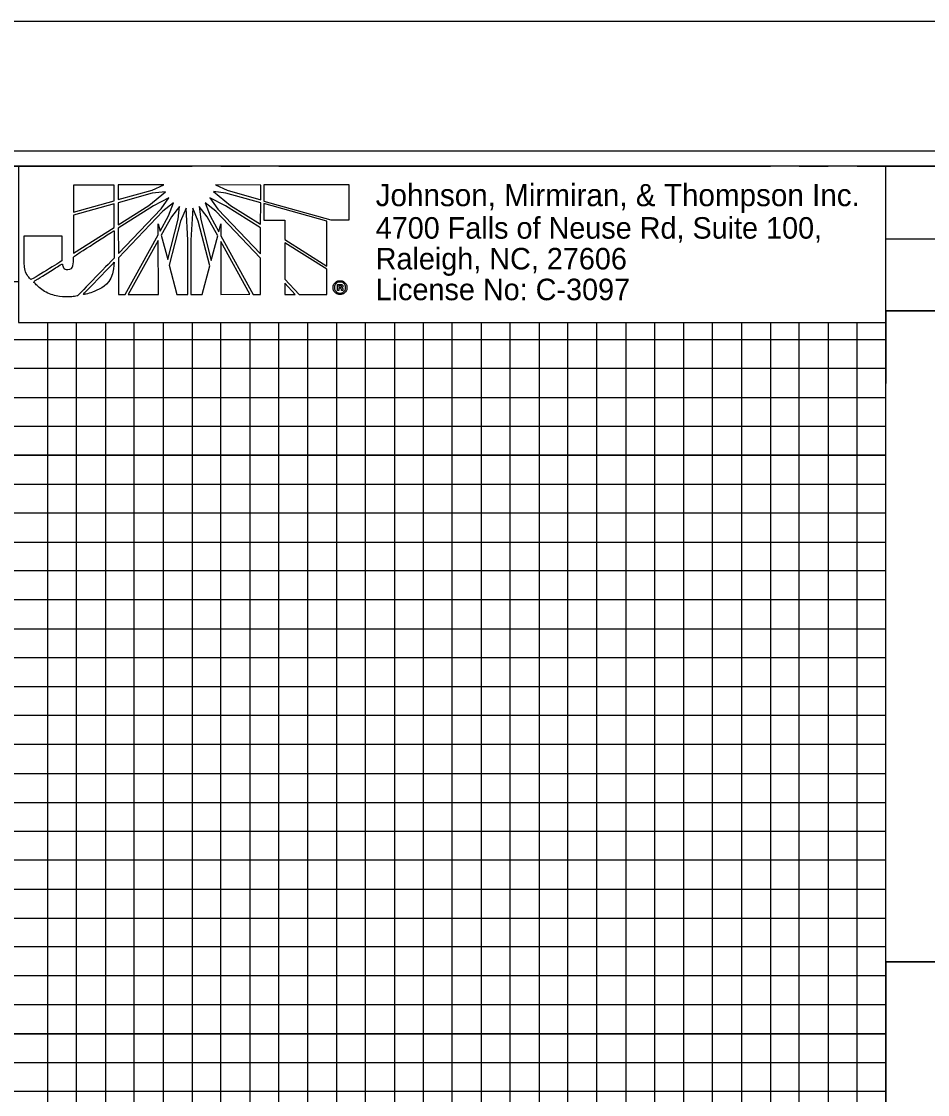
# Model space of a CAD drawing. Extents: x 1648862 to 1650855, y 808691 to 809791.
# Drawn here: x 1650179.8 to 1650336.5, y 809605.5 to 809791 of the extents above; entities that cross this region are included whole.
import ezdxf

# ---------------------------------------------------------------- set-up
doc = ezdxf.new("R2010")
doc.units = 0
for name, color, linetype in [('Prop Dimension Text', 7, 'Continuous'), ('Sheet Cutting Line CELL', 7, 'Continuous'), ('Sheet DOT Grid CELL', 7, 'Continuous'), ('Sheet Plan CELL', 7, 'Continuous'), ('Sheet Plot Border Inside CELL', 7, 'Continuous'), ('Sheet Plot Border Outside CELL', 7, 'Continuous'), ('Sheet Profile CELL', 7, 'Continuous'), ('Sheet Profile Grid Major CELL', 7, 'Continuous'), ('Sheet Profile Grid Middle CELL', 7, 'Continuous'), ('Sheet Profile Grid Minor CELL', 7, 'Continuous'), ('Sheet Sticker Exception Certification CELL', 7, 'Continuous')]:
    doc.layers.add(name, color=color, linetype=linetype)

msp = doc.modelspace()

# ---------------------------------------------------------------- linework, layer by layer
at = {"layer": 'Prop Dimension Text'}
for p, q in [((1650195.79, 809762.71), (1650188.77, 809762.7)), ((1650188.77, 809762.7), (1650188.77, 809758.05)), ((1650195.79, 809760), (1650195.79, 809762.71)), ((1650204.41, 809762.75), (1650196.52, 809762.75)), ((1650196.52, 809762.75), (1650196.52, 809760.23)), ((1650196.52, 809760.23), (1650202.4, 809761.86)), ((1650202.4, 809761.31), (1650196.52, 809759.69)), ((1650201.79, 809759.23), (1650204.69, 809761.59)), ((1650202.4, 809761.86), (1650204.41, 809762.75)), ((1650204.69, 809761.59), (1650202.4, 809761.31)), ((1650212.96, 809761.6), (1650215.9, 809759.2)), ((1650215.13, 809761.33), (1650212.96, 809761.6)), ((1650221.14, 809762.73), (1650213.35, 809762.76)), ((1650213.35, 809762.76), (1650215.32, 809761.84)), ((1650221.14, 809759.68), (1650215.13, 809761.33)), ((1650215.32, 809761.84), (1650221.14, 809760.21)), ((1650221.14, 809760.21), (1650221.14, 809762.73)), ((1650236.43, 809762.78), (1650221.68, 809762.77)), ((1650221.68, 809762.77), (1650221.68, 809760.06)), ((1650236.44, 809756.74), (1650236.43, 809762.78)), ((1650188.77, 809758.05), (1650195.79, 809760)), ((1650195.79, 809759.49), (1650188.77, 809757.52)), ((1650195.79, 809755.43), (1650195.79, 809759.49)), ((1650196.52, 809759.69), (1650196.52, 809755.89)), ((1650196.52, 809755.89), (1650201.79, 809759.23)), ((1650202.6, 809759.15), (1650196.52, 809755.28)), ((1650205.27, 809760.51), (1650202.6, 809759.15)), ((1650203.92, 809758.61), (1650205.27, 809760.51)), ((1650206.08, 809759.66), (1650204.22, 809758.22)), ((1650205.23, 809757.42), (1650206.08, 809759.66)), ((1650211.53, 809759.67), (1650212.39, 809757.42)), ((1650213.39, 809758.23), (1650211.53, 809759.67)), ((1650212.35, 809760.51), (1650213.71, 809758.58)), ((1650215.06, 809759.16), (1650212.35, 809760.51)), ((1650221.1, 809755.33), (1650215.06, 809759.16)), ((1650215.9, 809759.2), (1650221.1, 809755.96)), ((1650221.1, 809755.96), (1650221.14, 809759.68)), ((1650221.68, 809760.06), (1650221.68, 809759.98)), ((1650221.68, 809759.98), (1650233.3, 809756.74)), ((1650221.68, 809759.56), (1650221.68, 809759.52)), ((1650232.56, 809756.47), (1650221.68, 809759.56)), ((1650221.68, 809759.52), (1650221.69, 809756.69)), ((1650188.77, 809757.52), (1650188.78, 809750.97)), ((1650196.53, 809750.9), (1650203.92, 809758.61)), ((1650204.22, 809758.22), (1650196.53, 809750.16)), ((1650203.76, 809754.74), (1650205.23, 809757.42)), ((1650207.09, 809759.04), (1650205.7, 809757.25)), ((1650206.9, 809756.87), (1650207.09, 809759.04)), ((1650208.25, 809758.73), (1650207.29, 809756.48)), ((1650208.56, 809753.19), (1650208.25, 809758.73)), ((1650209.41, 809758.73), (1650209.05, 809753.19)), ((1650210.34, 809756.48), (1650209.41, 809758.73)), ((1650210.53, 809759.04), (1650210.77, 809756.8)), ((1650211.89, 809757.26), (1650210.53, 809759.04)), ((1650213.71, 809753.97), (1650211.89, 809757.26)), ((1650212.39, 809757.42), (1650213.89, 809754.63)), ((1650221.1, 809750.11), (1650213.39, 809758.23)), ((1650213.71, 809758.58), (1650221.1, 809750.84)), ((1650188.78, 809750.97), (1650195.79, 809755.43)), ((1650203.41, 809754.16), (1650203.41, 809756.01)), ((1650203.41, 809756.01), (1650203.76, 809754.74)), ((1650205.7, 809757.25), (1650203.96, 809754.08)), ((1650205.09, 809749.87), (1650206.9, 809756.87)), ((1650207.29, 809756.48), (1650205.32, 809748.89)), ((1650212.36, 809748.78), (1650210.34, 809756.48)), ((1650210.77, 809756.8), (1650212.59, 809749.71)), ((1650213.89, 809754.63), (1650214.25, 809756.02)), ((1650214.25, 809756.02), (1650214.25, 809753.97)), ((1650221.69, 809756.69), (1650225.29, 809756.69)), ((1650225.29, 809756.69), (1650225.29, 809753.32)), ((1650232.57, 809748.72), (1650232.56, 809756.47)), ((1650233.3, 809756.74), (1650236.44, 809756.74)), ((1650196.52, 809755.28), (1650196.53, 809750.9)), ((1650197.69, 809743.79), (1650203.41, 809754.16)), ((1650203.96, 809754.08), (1650205.09, 809749.87)), ((1650212.59, 809749.71), (1650213.71, 809753.97)), ((1650214.25, 809753.97), (1650219.87, 809743.81)), ((1650221.1, 809750.84), (1650221.1, 809755.33)), ((1650203.42, 809753.15), (1650198.24, 809743.79)), ((1650203.47, 809743.8), (1650203.42, 809753.15)), ((1650208.57, 809743.84), (1650208.56, 809753.19)), ((1650209.05, 809753.19), (1650209.06, 809743.84)), ((1650219.29, 809743.85), (1650214.25, 809752.97)), ((1650214.25, 809752.97), (1650214.26, 809743.84)), ((1650225.29, 809753.32), (1650232.57, 809748.72)), ((1650225.29, 809752.74), (1650225.3, 809746.47)), ((1650232.57, 809748.18), (1650225.29, 809752.74)), ((1650196.53, 809750.16), (1650196.53, 809743.79)), ((1650221.11, 809743.81), (1650221.1, 809750.11)), ((1650205.32, 809748.89), (1650206.64, 809743.83)), ((1650211.01, 809743.84), (1650212.36, 809748.78)), ((1650232.57, 809743.82), (1650232.57, 809748.18)), ((1650225.3, 809746.47), (1650227.81, 809743.82)), ((1650234.86, 809746.19), (1650234.86, 809745.97)), ((1650234.86, 809745.97), (1650234.86, 809746.19)), ((1650227.12, 809743.82), (1650225.3, 809745.78)), ((1650225.3, 809745.78), (1650225.3, 809743.82)), ((1650234.42, 809744.49), (1650234.42, 809745.56)), ((1650234.42, 809745.56), (1650234.86, 809745.56)), ((1650234.66, 809744.49), (1650234.42, 809744.49)), ((1650234.86, 809745.36), (1650234.66, 809745.36)), ((1650234.66, 809745.36), (1650234.66, 809745.1)), ((1650234.66, 809745.1), (1650234.86, 809745.1)), ((1650234.86, 809744.91), (1650234.66, 809744.91)), ((1650234.66, 809744.91), (1650234.66, 809744.49)), ((1650234.86, 809745.56), (1650234.86, 809745.36)), ((1650234.86, 809745.36), (1650234.86, 809745.56)), ((1650234.86, 809745.56), (1650234.92, 809745.56)), ((1650234.89, 809745.36), (1650234.86, 809745.36)), ((1650234.86, 809745.1), (1650234.86, 809744.91)), ((1650234.86, 809744.91), (1650234.86, 809745.1)), ((1650234.86, 809745.1), (1650234.87, 809745.1)), ((1650234.87, 809744.91), (1650234.86, 809744.91)), ((1650196.53, 809743.79), (1650197.69, 809743.79)), ((1650198.24, 809743.79), (1650203.47, 809743.8)), ((1650206.64, 809743.83), (1650208.57, 809743.84)), ((1650209.06, 809743.84), (1650211.01, 809743.84)), ((1650214.26, 809743.84), (1650219.29, 809743.85)), ((1650219.87, 809743.81), (1650221.11, 809743.81)), ((1650225.3, 809743.82), (1650227.12, 809743.82)), ((1650227.81, 809743.82), (1650232.57, 809743.82)), ((1650234.86, 809744.07), (1650234.86, 809743.83)), ((1650234.86, 809743.83), (1650234.86, 809744.07)), ((1650234.86, 809744.07), (1650234.87, 809744.07)), ((1650234.87, 809743.83), (1650234.86, 809743.83))]:
    msp.add_line(p, q, dxfattribs=at)
msp.add_lwpolyline([(1650179.28, 809738.96), (1650329.23, 809738.96), (1650329.23, 809766.02), (1650179.28, 809766.02)], close=True, dxfattribs=at)
for points in [[(1650188.77, 809758.05), (1650195.79, 809760), (1650195.79, 809762.71), (1650188.77, 809762.7), (1650188.77, 809758.05)], [(1650202.4, 809761.86), (1650204.41, 809762.75), (1650196.52, 809762.75), (1650196.52, 809760.23), (1650202.4, 809761.86)], [(1650196.52, 809759.69), (1650196.52, 809755.89), (1650201.79, 809759.23), (1650204.69, 809761.59), (1650202.4, 809761.31), (1650196.52, 809759.69)], [(1650212.96, 809761.6), (1650215.9, 809759.2), (1650221.1, 809755.96), (1650221.14, 809759.68), (1650215.13, 809761.33), (1650212.96, 809761.6)], [(1650215.32, 809761.84), (1650221.14, 809760.21), (1650221.14, 809762.73), (1650213.35, 809762.76), (1650215.32, 809761.84)], [(1650236.43, 809762.78), (1650221.68, 809762.77), (1650221.68, 809760.06), (1650221.68, 809759.98), (1650233.3, 809756.74), (1650236.44, 809756.74), (1650236.43, 809762.78)], [(1650188.78, 809750.97), (1650195.79, 809755.43), (1650195.79, 809759.49), (1650188.77, 809757.52), (1650188.78, 809750.97)], [(1650196.52, 809755.28), (1650196.53, 809750.9), (1650203.92, 809758.61), (1650205.27, 809760.51), (1650202.6, 809759.15), (1650196.52, 809755.28)], [(1650206.08, 809759.66), (1650204.22, 809758.22), (1650196.53, 809750.16), (1650196.53, 809743.79), (1650197.69, 809743.79), (1650203.41, 809754.16), (1650203.41, 809756.01), (1650203.76, 809754.74), (1650205.23, 809757.42), (1650206.08, 809759.66)], [(1650211.53, 809759.67), (1650212.39, 809757.42), (1650213.89, 809754.63), (1650214.25, 809756.02), (1650214.25, 809753.97), (1650219.87, 809743.81), (1650221.11, 809743.81), (1650221.1, 809750.11), (1650213.39, 809758.23), (1650211.53, 809759.67)], [(1650212.35, 809760.51), (1650213.71, 809758.58), (1650221.1, 809750.84), (1650221.1, 809755.33), (1650215.06, 809759.16), (1650212.35, 809760.51)], [(1650221.68, 809759.56), (1650221.68, 809759.52), (1650221.69, 809756.69), (1650225.29, 809756.69), (1650225.29, 809753.32), (1650232.57, 809748.72), (1650232.56, 809756.47), (1650221.68, 809759.56)], [(1650207.09, 809759.04), (1650205.7, 809757.25), (1650203.96, 809754.08), (1650205.09, 809749.87), (1650206.9, 809756.87), (1650207.09, 809759.04)], [(1650207.29, 809756.48), (1650205.32, 809748.89), (1650206.64, 809743.83), (1650208.57, 809743.84), (1650208.56, 809753.19), (1650208.25, 809758.73), (1650207.29, 809756.48)], [(1650209.41, 809758.73), (1650209.05, 809753.19), (1650209.06, 809743.84), (1650211.01, 809743.84), (1650212.36, 809748.78), (1650210.34, 809756.48), (1650209.41, 809758.73)], [(1650210.53, 809759.04), (1650210.77, 809756.8), (1650212.59, 809749.71), (1650213.71, 809753.97), (1650211.89, 809757.26), (1650210.53, 809759.04)], [(1650198.24, 809743.79), (1650203.47, 809743.8), (1650203.42, 809753.15), (1650198.24, 809743.79)], [(1650214.26, 809743.84), (1650219.29, 809743.85), (1650214.25, 809752.97), (1650214.26, 809743.84)], [(1650225.29, 809752.74), (1650225.3, 809746.47), (1650227.81, 809743.82), (1650232.57, 809743.82), (1650232.57, 809748.18), (1650225.29, 809752.74), (1650225.29, 809752.74)], [(1650225.3, 809743.82), (1650225.3, 809743.82), (1650227.12, 809743.82), (1650225.3, 809745.78), (1650225.3, 809743.82)], [(1650235.33, 809744.74), (1650235.33, 809744.68), (1650235.33, 809744.64), (1650235.33, 809744.61), (1650235.36, 809744.49), (1650235.14, 809744.49)]]:
    msp.add_lwpolyline(points, dxfattribs=at)
for points, degree in [([(1650186.76, 809753.98), (1650186.76, 809753.98), (1650180.27, 809753.98), (1650180.27, 809753.98), (1650180.27, 809753.98), (1650180.27, 809749.91), (1650180.27, 809749.91), (1650180.27, 809749.91), (1650180.27, 809749.48), (1650180.27, 809749.48), (1650180.27, 809748.21), (1650180.69, 809747.2), (1650181.43, 809746.36), (1650181.43, 809746.36), (1650186.77, 809749.6), (1650186.77, 809749.69), (1650186.77, 809749.69), (1650186.76, 809753.98), (1650186.76, 809753.98)], 3), ([(1650187.78, 809748.13), (1650187.36, 809748.13), (1650187, 809748.37), (1650186.85, 809749.14), (1650186.85, 809749.14), (1650181.81, 809746.02), (1650181.81, 809746.02), (1650183.37, 809744.39), (1650185.85, 809743.42), (1650187.94, 809743.42), (1650188.49, 809743.42), (1650188.9, 809743.47), (1650189.48, 809743.59), (1650189.48, 809743.59), (1650195.8, 809750.12), (1650195.8, 809750.12), (1650195.8, 809750.12), (1650195.79, 809754.85), (1650195.79, 809754.85), (1650195.79, 809754.85), (1650188.78, 809750.38), (1650188.78, 809750.38), (1650188.78, 809748.61), (1650188.35, 809748.14), (1650187.78, 809748.13)], 3), ([(1650187.78, 809748.13), (1650187.36, 809748.13), (1650187, 809748.37), (1650186.85, 809749.14), (1650186.85, 809749.14), (1650181.81, 809746.02), (1650181.81, 809746.02), (1650183.37, 809744.39), (1650185.85, 809743.42), (1650187.94, 809743.42), (1650188.49, 809743.42), (1650188.9, 809743.47), (1650189.48, 809743.59), (1650189.48, 809743.59), (1650195.8, 809750.12), (1650195.8, 809750.12), (1650195.8, 809750.12), (1650195.79, 809754.85), (1650195.79, 809754.85), (1650195.79, 809754.85), (1650188.78, 809750.38), (1650188.78, 809750.38), (1650188.78, 809748.61), (1650188.35, 809748.14), (1650187.78, 809748.13)], 3), ([(1650195.8, 809749.38), (1650195.8, 809749.38), (1650190.34, 809743.74), (1650190.34, 809743.74), (1650193.01, 809744.4), (1650195.68, 809746.17), (1650195.8, 809749.38)], 3), ([(1650234.86, 809743.83), (1650234.54, 809743.83), (1650234.25, 809743.95), (1650234.02, 809744.18), (1650233.78, 809744.41), (1650233.67, 809744.69), (1650233.67, 809745.02), (1650233.67, 809745.35), (1650233.78, 809745.64), (1650234.02, 809745.85), (1650234.25, 809746.08), (1650234.52, 809746.19), (1650234.86, 809746.19)], 3), ([(1650234.86, 809746.19), (1650235.19, 809746.19), (1650235.47, 809746.08), (1650235.7, 809745.85), (1650235.94, 809745.64), (1650236.06, 809745.36), (1650236.06, 809745.03)], 3), ([(1650234.86, 809745.97), (1650234.59, 809745.97), (1650234.37, 809745.88), (1650234.18, 809745.71), (1650234, 809745.52), (1650233.9, 809745.29), (1650233.9, 809745.02), (1650233.9, 809744.76), (1650234, 809744.53), (1650234.18, 809744.34), (1650234.37, 809744.16), (1650234.59, 809744.07), (1650234.86, 809744.07)], 3), ([(1650234.87, 809744.07), (1650235.13, 809744.07), (1650235.35, 809744.16), (1650235.54, 809744.34), (1650235.72, 809744.53), (1650235.82, 809744.76), (1650235.82, 809745.03), (1650235.82, 809745.29), (1650235.72, 809745.52), (1650235.54, 809745.71), (1650235.35, 809745.88), (1650235.13, 809745.97), (1650234.86, 809745.97)], 3), ([(1650234.87, 809745.1), (1650235.02, 809745.1), (1650235.1, 809745.15), (1650235.1, 809745.24), (1650235.1, 809745.32), (1650235.03, 809745.36), (1650234.89, 809745.36)], 3), ([(1650236.06, 809745.03), (1650236.06, 809744.69), (1650235.94, 809744.41), (1650235.72, 809744.18), (1650235.48, 809743.95), (1650235.2, 809743.83), (1650234.87, 809743.83)], 3), ([(1650235.05, 809744.87), (1650235.02, 809744.89), (1650234.96, 809744.91), (1650234.87, 809744.91)], 2), ([(1650234.92, 809745.56), (1650235.2, 809745.56), (1650235.33, 809745.45), (1650235.33, 809745.24), (1650235.33, 809745.14), (1650235.3, 809745.06), (1650235.21, 809745)], 3), ([(1650235.14, 809744.49), (1650235.11, 809744.55), (1650235.09, 809744.61), (1650235.09, 809744.68), (1650235.09, 809744.78), (1650235.08, 809744.84), (1650235.05, 809744.87)], 3), ([(1650235.21, 809745), (1650235.28, 809744.97), (1650235.32, 809744.88), (1650235.33, 809744.74)], 2)]:
    msp.add_open_spline(points, degree=degree, dxfattribs=at)
at = {"layer": 'Sheet Cutting Line CELL'}
msp.add_line((1650546.28, 809791.02), (1648862.28, 809791.02), dxfattribs=at)
at = {"layer": 'Sheet DOT Grid CELL'}
for p, q in [((1650229.28, 809266.02), (1650229.28, 809738.96)), ((1650279.28, 809266.02), (1650279.28, 809738.96)), ((1650229.28, 809266.02), (1650229.28, 809718.48)), ((1650229.28, 809266.02), (1650229.28, 809718.48)), ((1650279.28, 809266.02), (1650279.28, 809718.48)), ((1650279.28, 809266.02), (1650279.28, 809718.48)), ((1650329.23, 809716.02), (1649029.28, 809716.02)), ((1650329.23, 809716.02), (1649029.28, 809716.02)), ((1650329.23, 809716.02), (1649029.28, 809716.02)), ((1650329.23, 809666.02), (1649029.28, 809666.02)), ((1650329.23, 809666.02), (1649029.28, 809666.02)), ((1650329.23, 809666.02), (1649029.28, 809666.02)), ((1650329.28, 809266.02), (1650329.28, 809628.47)), ((1650329.28, 809266.02), (1650329.28, 809628.47)), ((1650329.28, 809266.02), (1650329.28, 809628.47)), ((1650329.28, 809616.02), (1649029.28, 809616.02)), ((1650329.28, 809616.02), (1649029.28, 809616.02)), ((1650329.28, 809616.02), (1649029.28, 809616.02))]:
    msp.add_line(p, q, dxfattribs=at)
at = {"layer": 'Sheet Plan CELL'}
msp.add_line((1650329.23, 809740.94), (1650329.23, 809728.45), dxfattribs=at)
msp.add_line((1650329.23, 809740.94), (1650329.23, 809728.45), dxfattribs=at)
msp.add_line((1650329.23, 809740.94), (1650329.23, 809728.45), dxfattribs=at)
at = {"layer": 'Sheet Plot Border Inside CELL'}
msp.add_lwpolyline([(1648875.28, 808713.47), (1650541.78, 808713.47), (1650541.78, 809768.57), (1648875.28, 809768.57)], close=True, dxfattribs=at)
at = {"layer": 'Sheet Plot Border Outside CELL'}
msp.add_lwpolyline([(1648862.28, 808691.02), (1650546.28, 808691.02), (1650546.28, 809791.02), (1648862.28, 809791.02)], close=True, dxfattribs=at)
at = {"layer": 'Sheet Profile CELL'}
msp.add_line((1650329.23, 809753.47), (1650529.28, 809753.47), dxfattribs=at)
for points in [[(1650529.28, 809766.02), (1649029.28, 809766.02), (1649029.28, 808716.02), (1650529.28, 808716.02)], [(1650329.23, 809766.02), (1650529.28, 809766.02), (1650529.28, 809740.97), (1650329.23, 809740.97)], [(1650329.23, 809740.97), (1650429.28, 809740.97), (1650429.28, 809628.47), (1650329.23, 809628.47)]]:
    msp.add_lwpolyline(points, close=True, dxfattribs=at)
at = {"layer": 'Sheet Profile Grid Major CELL'}
for points in [[(1650229.28, 809766.02), (1650279.28, 809766.02)], [(1650279.23, 809738.96), (1650279.23, 809266.02), (1650329.23, 809266.02), (1650329.23, 809766.02), (1650355.53, 809766.02)], [(1650179.28, 809266.02), (1650229.28, 809266.02), (1650229.28, 809738.96)], [(1649029.28, 809716.02), (1650329.28, 809716.02)], [(1650329.28, 809666.02), (1649029.28, 809666.02), (1649029.28, 809616.02), (1650329.28, 809616.02)]]:
    msp.add_lwpolyline(points, dxfattribs=at)
at = {"layer": 'Sheet Profile Grid Middle CELL'}
for points in [[(1650154.28, 809766.02), (1650204.28, 809766.02)], [(1650254.28, 809766.02), (1650304.28, 809766.02)], [(1650204.28, 809738.96), (1650204.28, 809266.02), (1650254.28, 809266.02), (1650254.28, 809738.96)], [(1650304.28, 809738.96), (1650304.28, 809266.02), (1650354.28, 809266.02), (1650354.28, 809604.97)], [(1650329.28, 809691.02), (1649029.28, 809691.02), (1649029.28, 809641.02), (1650329.28, 809641.02)]]:
    msp.add_lwpolyline(points, dxfattribs=at)
at = {"layer": 'Sheet Profile Grid Minor CELL'}
for p, q in [((1650329.23, 809761.02), (1650329.28, 809761.02)), ((1650329.28, 809756.02), (1650329.23, 809756.02)), ((1650329.23, 809751.02), (1650329.28, 809751.02)), ((1650329.23, 809631.02), (1649079.28, 809631.02)), ((1650329.28, 809626.02), (1649079.28, 809626.02)), ((1650329.28, 809621.02), (1649079.28, 809621.02)), ((1649079.28, 809611.02), (1650329.28, 809611.02)), ((1650329.28, 809606.02), (1649079.28, 809606.02))]:
    msp.add_line(p, q, dxfattribs=at)
for points in [[(1650174.28, 809766.02), (1650184.28, 809766.02)], [(1650189.28, 809766.02), (1650194.28, 809766.02)], [(1650199.28, 809766.02), (1650209.28, 809766.02)], [(1650214.28, 809766.02), (1650219.28, 809766.02)], [(1650224.28, 809766.02), (1650234.28, 809766.02)], [(1650239.28, 809766.02), (1650244.28, 809766.02)], [(1650249.28, 809766.02), (1650259.28, 809766.02)], [(1650264.28, 809766.02), (1650269.28, 809766.02)], [(1650274.28, 809766.02), (1650284.28, 809766.02)], [(1650289.28, 809766.02), (1650294.28, 809766.02)], [(1650299.28, 809766.02), (1650309.28, 809766.02)], [(1650314.28, 809766.02), (1650319.28, 809766.02)], [(1650324.28, 809766.02), (1650334.28, 809766.02)], [(1650179.28, 809746.02), (1649079.28, 809746.02), (1649079.28, 809736.02), (1650329.28, 809736.02)], [(1650329.28, 809746.02), (1650329.23, 809746.02)], [(1650184.28, 809738.96), (1650184.28, 809266.02), (1650189.28, 809266.02), (1650189.28, 809738.96)], [(1650194.28, 809738.96), (1650194.28, 809266.02), (1650199.28, 809266.02), (1650199.28, 809738.96)], [(1650209.28, 809738.96), (1650209.28, 809266.02), (1650214.28, 809266.02), (1650214.28, 809738.96)], [(1650219.28, 809266.02), (1650224.28, 809266.02), (1650224.28, 809738.96)], [(1650219.28, 809738.96), (1650219.28, 809266.02)], [(1650234.28, 809738.96), (1650234.28, 809266.02), (1650239.28, 809266.02), (1650239.28, 809738.96)], [(1650244.28, 809738.96), (1650244.28, 809266.02), (1650249.28, 809266.02), (1650249.28, 809738.96)], [(1650259.28, 809738.96), (1650259.28, 809266.02), (1650264.28, 809266.02), (1650264.28, 809738.96)], [(1650269.28, 809738.96), (1650269.28, 809266.02), (1650274.28, 809266.02), (1650274.28, 809738.96)], [(1650284.28, 809738.96), (1650284.28, 809266.02), (1650289.28, 809266.02), (1650289.28, 809738.96)], [(1650294.28, 809738.96), (1650294.28, 809266.02), (1650299.28, 809266.02), (1650299.28, 809738.96)], [(1650309.28, 809738.96), (1650309.28, 809266.02), (1650314.28, 809266.02), (1650314.28, 809738.96)], [(1650319.28, 809738.96), (1650319.28, 809266.02), (1650324.28, 809266.02), (1650324.28, 809738.96)], [(1650329.23, 809731.02), (1649079.28, 809731.02), (1649079.28, 809726.02), (1650329.28, 809726.02)], [(1650329.28, 809721.02), (1649079.28, 809721.02), (1649079.28, 809711.02), (1650329.28, 809711.02)], [(1650329.28, 809706.02), (1649079.28, 809706.02), (1649079.28, 809701.02), (1650329.28, 809701.02)], [(1650329.28, 809696.02), (1649079.28, 809696.02), (1649079.28, 809686.02), (1650329.28, 809686.02)], [(1650329.28, 809681.02), (1649079.28, 809681.02), (1649079.28, 809676.02), (1650329.28, 809676.02)], [(1650329.28, 809671.02), (1649079.28, 809671.02), (1649079.28, 809661.02), (1650329.28, 809661.02)], [(1650329.28, 809655.92), (1649079.38, 809655.92), (1649079.38, 809651.02), (1650329.28, 809651.02)], [(1650329.28, 809646.02), (1649079.28, 809646.02), (1649079.28, 809636.02), (1650329.28, 809636.02)]]:
    msp.add_lwpolyline(points, dxfattribs=at)
at = {"layer": 'Sheet Sticker Exception Certification CELL'}
for p, q in [((1650329.23, 809604.97), (1650329.23, 809628.47)), ((1650329.23, 809628.47), (1650529.27, 809628.47)), ((1650329.23, 809604.97), (1650329.23, 809628.47)), ((1650329.23, 809628.47), (1650529.27, 809628.47))]:
    msp.add_line(p, q, dxfattribs=at)

# ---------------------------------------------------------------- texts
at = {"layer": 'Prop Dimension Text'}
for s, height, p in [('Johnson, Mirmiran, & Thompson Inc.', 3.8315, (1650241.03, 809759.09)), ('4700 Falls of Neuse Rd, Suite 100, ', 3.722, (1650241.03, 809753.47)), ('Raleigh, NC, 27606', 3.722, (1650241.03, 809748.15)), ('License No: C-3097', 3.722, (1650241.03, 809742.83))]:
    msp.add_text(s, height=height, rotation=360, dxfattribs=at).set_placement(p)

doc.saveas('drawing.dxf')
